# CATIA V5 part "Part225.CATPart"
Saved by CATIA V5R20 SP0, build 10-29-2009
Part number: FA 168700-1
Revision: ANY
Definition: UNKNOWN
Nomenclature: FA 168700-1
Source: Unknown
Bounding box of the stored display mesh (mm): x -3.804 to 3.804, y 0.28 to 2.5, z -4 to 4
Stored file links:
  C:\Users\Utente\Desktop\IO LAVORO\3D X SITO CF\CUMSA\3D files FA\FA 200712-20\Part225.CATPart
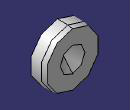
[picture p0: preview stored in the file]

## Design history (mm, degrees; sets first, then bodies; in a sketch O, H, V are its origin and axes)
Body1 "Cortar-Extruir1" (main body)
  Solid1: solid without history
